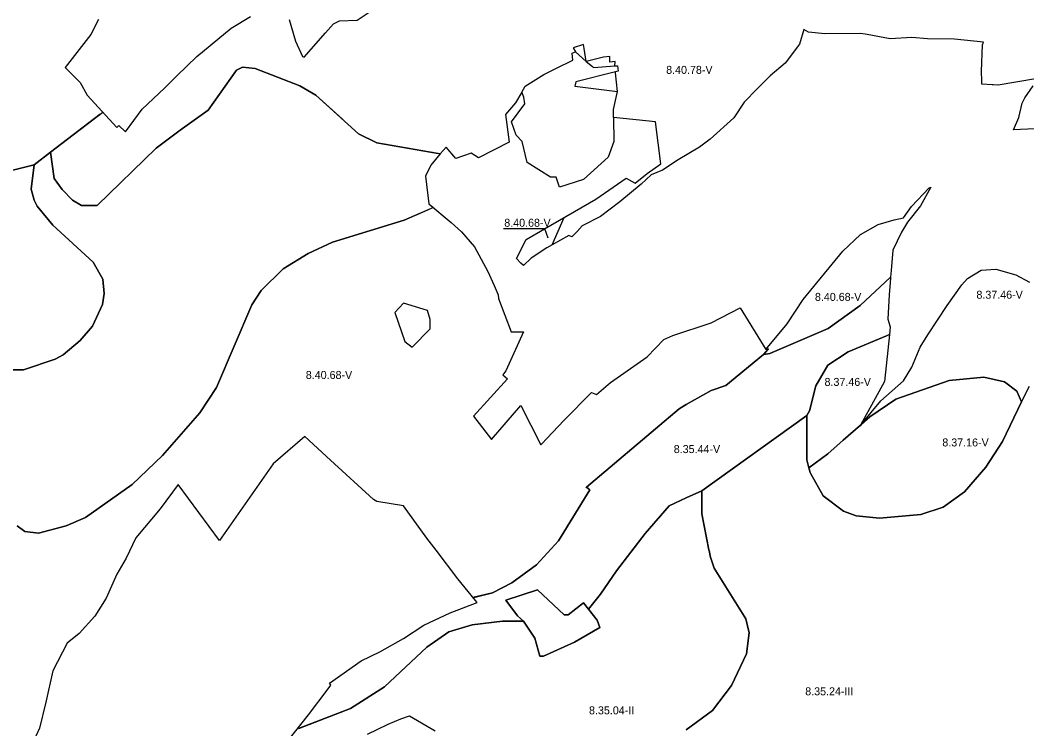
# Model space of a CAD drawing. Extents: x -547623 to -533936, y -1096714 to -1086523.
# Drawn here: x -545832 to -544574, y -1095680 to -1094794 of the extents above; entities that cross this region are included whole.
import ezdxf

# ---------------------------------------------------------------- set-up
doc = ezdxf.new("R2010")
doc.units = 0
doc.layers.add('Vrstva 27', color=7, linetype='Continuous')
doc.layers.add('Vrstva 28', color=7, linetype='Continuous')

msp = doc.modelspace()

# ---------------------------------------------------------------- linework, layer by layer
at = {"layer": 'Vrstva 27'}
msp.add_lwpolyline([(-545228.3, -1095054.4), (-545177.3, -1095054.4), (-545173.1, -1095066.3)], dxfattribs=at)
at = {"layer": 'Vrstva 28'}
for p, q in [((-545597.5, -1094906.5), (-545562, -1094856.5)), ((-545562, -1094856.5), (-545597.5, -1094906.5)), ((-545562, -1094856.5), (-545554.5, -1094853)), ((-545554.5, -1094853), (-545562, -1094856.5)), ((-545554.5, -1094853), (-545538.5, -1094854.5)), ((-545538.5, -1094854.5), (-545554.5, -1094853)), ((-545538.5, -1094854.5), (-545483, -1094876)), ((-545483, -1094876), (-545538.5, -1094854.5)), ((-545483, -1094876), (-545463, -1094888)), ((-545463, -1094888), (-545483, -1094876)), ((-545463, -1094888), (-545409.5, -1094936)), ((-545409.5, -1094936), (-545463, -1094888)), ((-545794.5, -1094959), (-545729, -1094909.2)), ((-545632.5, -1094931.5), (-545597.5, -1094906.5)), ((-545597.5, -1094906.5), (-545632.5, -1094931.5)), ((-545662.5, -1094954), (-545632.5, -1094931.5)), ((-545632.5, -1094931.5), (-545662.5, -1094954)), ((-545409.5, -1094936), (-545386.5, -1094947.5)), ((-545386.5, -1094947.5), (-545409.5, -1094936)), ((-545386.5, -1094947.5), (-545309.8, -1094960.7)), ((-545309.8, -1094960.7), (-545386.5, -1094947.5)), ((-545815, -1094975), (-545794.5, -1094959)), ((-545794.5, -1094959), (-545790, -1094992)), ((-545790, -1094992), (-545794.5, -1094959)), ((-545736, -1095026), (-545662.5, -1094954)), ((-545662.5, -1094954), (-545736, -1095026)), ((-545307.3, -1094961.2), (-545309.8, -1094960.7)), ((-545845, -1094982.5), (-545815, -1094975)), ((-545815, -1094975), (-545818.5, -1095005.5)), ((-545818.5, -1095005.5), (-545815, -1094975)), ((-545790, -1094992), (-545780, -1095006)), ((-545780, -1095006), (-545790, -1094992)), ((-545818.5, -1095005.5), (-545815, -1095019)), ((-545815, -1095019), (-545818.5, -1095005.5)), ((-545780, -1095006), (-545767, -1095019)), ((-545767, -1095019), (-545780, -1095006)), ((-545815, -1095019), (-545811, -1095026.5)), ((-545811, -1095026.5), (-545815, -1095019)), ((-545811, -1095026.5), (-545791.5, -1095050.5)), ((-545791.5, -1095050.5), (-545811, -1095026.5)), ((-545767, -1095019), (-545755.5, -1095026)), ((-545755.5, -1095026), (-545767, -1095019)), ((-545755.5, -1095026), (-545736, -1095026)), ((-545736, -1095026), (-545755.5, -1095026)), ((-545315.9, -1095028.4), (-545352.5, -1095044)), ((-545352.5, -1095044), (-545322.9, -1095031.4)), ((-545791.5, -1095050.5), (-545741, -1095096.5)), ((-545741, -1095096.5), (-545791.5, -1095050.5)), ((-545352.5, -1095044), (-545442, -1095071.5)), ((-545442, -1095071.5), (-545352.5, -1095044)), ((-545442, -1095071.5), (-545472.5, -1095086)), ((-545472.5, -1095086), (-545442, -1095071.5)), ((-545472.5, -1095086), (-545503.5, -1095105)), ((-545503.5, -1095105), (-545472.5, -1095086)), ((-545741, -1095096.5), (-545729, -1095118)), ((-545729, -1095118), (-545741, -1095096.5)), ((-545503.5, -1095105), (-545531, -1095132)), ((-545531, -1095132), (-545503.5, -1095105)), ((-545729, -1095118), (-545727.5, -1095136)), ((-545727.5, -1095136), (-545729, -1095118)), ((-544782.5, -1095151), (-544744.8, -1095115.5)), ((-544744.8, -1095115.5), (-544782.5, -1095151)), ((-545727.5, -1095136), (-545729.5, -1095149.5)), ((-545729.5, -1095149.5), (-545727.5, -1095136)), ((-545531, -1095132), (-545543, -1095150)), ((-545543, -1095150), (-545531, -1095132)), ((-545729.5, -1095149.5), (-545742, -1095176.5)), ((-545742, -1095176.5), (-545729.5, -1095149.5)), ((-545543, -1095150), (-545587, -1095253.5)), ((-545587, -1095253.5), (-545543, -1095150)), ((-544822.5, -1095179.5), (-544782.5, -1095151)), ((-544782.5, -1095151), (-544822.5, -1095179.5)), ((-545742, -1095176.5), (-545757.5, -1095194.5)), ((-545757.5, -1095194.5), (-545742, -1095176.5)), ((-544895.5, -1095211), (-544822.5, -1095179.5)), ((-544822.5, -1095179.5), (-544895.5, -1095211)), ((-544749.7, -1095188.6), (-544797.5, -1095209)), ((-544797.5, -1095209), (-544749.7, -1095188.6)), ((-544746.2, -1095187.1), (-544749.7, -1095188.6)), ((-544749.7, -1095188.6), (-544746.2, -1095187.1)), ((-545757.5, -1095194.5), (-545778.5, -1095212.5)), ((-545778.5, -1095212.5), (-545757.5, -1095194.5)), ((-545778.5, -1095212.5), (-545788.5, -1095218)), ((-545788.5, -1095218), (-545778.5, -1095212.5)), ((-544950.5, -1095251), (-544903.5, -1095212)), ((-544903.5, -1095212), (-544950.5, -1095251)), ((-544903.5, -1095212), (-544897.5, -1095205.5)), ((-544897.5, -1095205.5), (-544903.5, -1095212)), ((-544903.5, -1095212), (-544895.5, -1095211)), ((-544895.5, -1095211), (-544903.5, -1095212)), ((-544897.5, -1095205.5), (-544898.6, -1095203.6)), ((-544898.1, -1095204.5), (-544897.5, -1095205.5)), ((-544797.5, -1095209), (-544823, -1095225.5)), ((-544823, -1095225.5), (-544797.5, -1095209)), ((-545788.5, -1095218), (-545828, -1095231.5)), ((-545828, -1095231.5), (-545788.5, -1095218)), ((-544823, -1095225.5), (-544838, -1095251.5)), ((-544838, -1095251.5), (-544823, -1095225.5)), ((-545828, -1095231.5), (-545842.5, -1095231.5)), ((-545842.5, -1095231.5), (-545828, -1095231.5)), ((-544671.5, -1095244.5), (-544628, -1095240.5)), ((-544628, -1095240.5), (-544671.5, -1095244.5)), ((-544628, -1095240.5), (-544602.5, -1095246.5)), ((-544602.5, -1095246.5), (-544628, -1095240.5)), ((-545587, -1095253.5), (-545608, -1095285)), ((-545608, -1095285), (-545587, -1095253.5)), ((-544969, -1095257), (-544950.5, -1095251)), ((-544950.5, -1095251), (-544969, -1095257)), ((-544838, -1095251.5), (-544846, -1095282.5)), ((-544846, -1095282.5), (-544838, -1095251.5)), ((-544738, -1095268), (-544671.5, -1095244.5)), ((-544671.5, -1095244.5), (-544738, -1095268)), ((-544602.5, -1095246.5), (-544587, -1095258)), ((-544587, -1095258), (-544602.5, -1095246.5)), ((-544581, -1095271.5), (-544571.5, -1095252)), ((-544571.5, -1095252), (-544581, -1095271.5)), ((-545000, -1095274.8), (-544969, -1095257)), ((-544969, -1095257), (-545000, -1095274.8)), ((-544587, -1095258), (-544581, -1095271.5)), ((-544581, -1095271.5), (-544587, -1095258)), ((-545009, -1095280), (-545000, -1095274.8)), ((-545000, -1095274.8), (-545009, -1095280)), ((-544770.5, -1095290), (-544738, -1095268)), ((-544738, -1095268), (-544770.5, -1095290)), ((-544605, -1095321), (-544581, -1095271.5)), ((-544581, -1095271.5), (-544605, -1095321)), ((-545608, -1095285), (-545654.5, -1095338.5)), ((-545654.5, -1095338.5), (-545608, -1095285)), ((-545038.5, -1095305), (-545009, -1095280)), ((-545009, -1095280), (-545038.5, -1095305)), ((-544980.5, -1095382.5), (-544849.5, -1095288.5)), ((-544849.5, -1095288.5), (-544980.5, -1095382.5)), ((-544846, -1095282.5), (-544849.5, -1095288.5)), ((-544849.5, -1095288.5), (-544846, -1095282.5)), ((-544849.5, -1095288.5), (-544849.5, -1095344)), ((-544849.5, -1095344), (-544849.5, -1095288.5)), ((-544781, -1095299.3), (-544770.5, -1095290)), ((-544770.5, -1095290), (-544781, -1095299.3)), ((-544804, -1095319.3), (-544782.1, -1095300.3)), ((-544782.1, -1095300.3), (-544804, -1095319.3)), ((-544782.1, -1095300.3), (-544782.1, -1095300.3)), ((-544782.1, -1095300.3), (-544782.1, -1095300.3)), ((-544782.1, -1095300.3), (-544782.1, -1095300.3)), ((-545124.5, -1095378), (-545038.5, -1095305)), ((-545038.5, -1095305), (-545124.5, -1095378)), ((-544823.2, -1095336.2), (-544804, -1095319.3)), ((-544804, -1095319.3), (-544823.2, -1095336.2)), ((-544625.5, -1095353), (-544605, -1095321)), ((-544605, -1095321), (-544625.5, -1095353)), ((-545654.5, -1095338.5), (-545692.5, -1095374.5)), ((-545692.5, -1095374.5), (-545654.5, -1095338.5)), ((-544846.7, -1095353.9), (-544823.2, -1095336.2)), ((-544823.2, -1095336.2), (-544846.7, -1095353.9)), ((-544849.5, -1095344), (-544846.7, -1095353.9)), ((-544846.7, -1095353.9), (-544849.5, -1095344)), ((-544846.7, -1095353.9), (-544845, -1095359.7)), ((-544845, -1095359.7), (-544846.7, -1095353.9)), ((-544652.5, -1095384), (-544625.5, -1095353)), ((-544625.5, -1095353), (-544652.5, -1095384)), ((-544845, -1095359.7), (-544844.5, -1095361.5)), ((-544844.5, -1095361.5), (-544845, -1095359.7)), ((-544844.5, -1095361.5), (-544829, -1095389)), ((-544829, -1095389), (-544844.5, -1095361.5)), ((-545692.5, -1095374.5), (-545750.5, -1095416)), ((-545750.5, -1095416), (-545692.5, -1095374.5)), ((-545124.5, -1095378), (-545125.3, -1095378.7)), ((-545120.5, -1095381.5), (-545124.5, -1095378)), ((-545124.5, -1095378), (-545120.5, -1095381.5)), ((-545159.5, -1095445), (-545120.5, -1095381.5)), ((-545120.5, -1095381.5), (-545159.5, -1095445)), ((-545021.5, -1095401.5), (-545000, -1095391.5)), ((-545000, -1095391.5), (-545021.5, -1095401.5)), ((-545000, -1095391.5), (-544980.5, -1095382.5)), ((-544980.5, -1095382.5), (-545000, -1095391.5)), ((-544980.5, -1095382.5), (-544980.5, -1095411.5)), ((-544980.5, -1095411.5), (-544980.5, -1095382.5)), ((-544829, -1095389), (-544803.5, -1095408)), ((-544803.5, -1095408), (-544829, -1095389)), ((-544679, -1095403), (-544652.5, -1095384)), ((-544652.5, -1095384), (-544679, -1095403)), ((-545051.5, -1095436), (-545021.5, -1095401.5)), ((-545021.5, -1095401.5), (-545051.5, -1095436)), ((-544707, -1095412), (-544679, -1095403)), ((-544679, -1095403), (-544707, -1095412)), ((-545750.5, -1095416), (-545775, -1095426.5)), ((-545775, -1095426.5), (-545750.5, -1095416)), ((-544980.5, -1095411.5), (-544971.6, -1095456.2)), ((-544971.6, -1095456.2), (-544980.5, -1095411.5)), ((-544803.5, -1095408), (-544787.5, -1095414)), ((-544787.5, -1095414), (-544803.5, -1095408)), ((-544787.5, -1095414), (-544758.5, -1095417)), ((-544758.5, -1095417), (-544787.5, -1095414)), ((-544758.5, -1095417), (-544707, -1095412)), ((-544707, -1095412), (-544758.5, -1095417)), ((-545826.5, -1095433.5), (-545836, -1095426.5)), ((-545836, -1095426.5), (-545826.5, -1095433.5)), ((-545775, -1095426.5), (-545809.5, -1095435.5)), ((-545809.5, -1095435.5), (-545775, -1095426.5)), ((-545809.5, -1095435.5), (-545826.5, -1095433.5)), ((-545826.5, -1095433.5), (-545809.5, -1095435.5)), ((-545087, -1095482.5), (-545051.5, -1095436)), ((-545051.5, -1095436), (-545087, -1095482.5)), ((-545187, -1095475), (-545159.5, -1095445)), ((-545159.5, -1095445), (-545187, -1095475)), ((-544971.6, -1095456.2), (-544971.1, -1095459)), ((-544971.1, -1095459), (-544971.6, -1095456.2)), ((-544971.1, -1095459), (-544970, -1095464.5)), ((-544970, -1095464.5), (-544971.1, -1095459)), ((-544970, -1095464.5), (-544965, -1095479.5)), ((-544965, -1095479.5), (-544970, -1095464.5)), ((-545218, -1095497.5), (-545187, -1095475)), ((-545187, -1095475), (-545218, -1095497.5)), ((-544965, -1095479.5), (-544925.5, -1095542.5)), ((-544925.5, -1095542.5), (-544965, -1095479.5)), ((-545107, -1095512), (-545087, -1095482.5)), ((-545087, -1095482.5), (-545107, -1095512)), ((-545242, -1095510), (-545218, -1095497.5)), ((-545218, -1095497.5), (-545242, -1095510)), ((-545242, -1095510), (-545266.5, -1095516)), ((-545225.5, -1095519.5), (-545186, -1095506.5)), ((-545186, -1095506.5), (-545152.5, -1095537.5)), ((-545122.2, -1095530.7), (-545107, -1095512)), ((-545107, -1095512), (-545122.2, -1095530.7)), ((-545211, -1095539), (-545225.5, -1095519.5)), ((-545128.5, -1095522.5), (-545147.5, -1095537.5)), ((-545147.5, -1095537.5), (-545128.5, -1095522.5)), ((-545122.2, -1095530.7), (-545128.5, -1095522.5)), ((-545128.5, -1095522.5), (-545122.2, -1095530.7)), ((-545211, -1095539), (-545203.5, -1095545.5)), ((-545203.5, -1095545.5), (-545211, -1095539)), ((-545147.5, -1095537.5), (-545152.5, -1095537.5)), ((-545152.5, -1095537.5), (-545147.5, -1095537.5)), ((-545111.5, -1095544.5), (-545122.2, -1095530.7)), ((-545122.2, -1095530.7), (-545111.5, -1095544.5)), ((-544925.5, -1095542.5), (-544921.5, -1095560)), ((-544921.5, -1095560), (-544925.5, -1095542.5)), ((-545267.5, -1095550), (-545296.5, -1095559)), ((-545229.5, -1095545.5), (-545267.5, -1095550)), ((-545203.5, -1095545.5), (-545229.5, -1095545.5)), ((-545203.5, -1095545.5), (-545189, -1095567)), ((-545189, -1095567), (-545203.5, -1095545.5)), ((-545139.5, -1095572), (-545108, -1095553.5)), ((-545108, -1095553.5), (-545139.5, -1095572)), ((-545108, -1095553.5), (-545111.5, -1095544.5)), ((-545111.5, -1095544.5), (-545108, -1095553.5)), ((-545296.5, -1095559), (-545324, -1095578)), ((-545189, -1095567), (-545183, -1095589.5)), ((-545183, -1095589.5), (-545189, -1095567)), ((-544921.5, -1095560), (-544924.5, -1095586.5)), ((-544924.5, -1095586.5), (-544921.5, -1095560)), ((-545324, -1095578), (-545377, -1095627.5)), ((-545178.5, -1095589.5), (-545139.5, -1095572)), ((-545139.5, -1095572), (-545178.5, -1095589.5)), ((-545183, -1095589.5), (-545178.5, -1095589.5)), ((-545178.5, -1095589.5), (-545183, -1095589.5)), ((-544924.5, -1095586.5), (-544943.5, -1095626)), ((-544943.5, -1095626), (-544924.5, -1095586.5)), ((-545377, -1095627.5), (-545419.5, -1095655)), ((-544943.5, -1095626), (-544967, -1095657.5)), ((-544967, -1095657.5), (-544943.5, -1095626)), ((-545419.5, -1095655), (-545484.5, -1095679.9)), ((-544967, -1095657.5), (-545000, -1095681.3)), ((-545000, -1095681.3), (-544967, -1095657.5))]:
    msp.add_line(p, q, dxfattribs=at)
for points in [[(-545496, -1094793.4), (-545488.2, -1094820.5), (-545479.4, -1094839.5), (-545477.6, -1094840.2), (-545450.7, -1094809.9), (-545440.8, -1094798.6), (-545433.3, -1094795), (-545411.4, -1094794), (-545391.2, -1094780.8)], [(-545734.6, -1094793.4), (-545744.1, -1094812.1), (-545776.1, -1094853.2), (-545757.5, -1094871.9), (-545748.7, -1094887.7), (-545711.5, -1094928.4), (-545708.9, -1094925.6), (-545700.5, -1094933.9), (-545680, -1094905.5), (-545652, -1094879.2), (-545636.5, -1094863.8), (-545611.7, -1094839.5), (-545568.6, -1094803.9), (-545544.4, -1094789.6)], [(-544617.6, -1094874.8), (-544630.7, -1094874), (-544630.8, -1094870.1), (-544631.1, -1094858.4), (-544631.5, -1094858.4), (-544631.1, -1094858.4), (-544631.2, -1094858.3), (-544629.8, -1094825.1), (-544628.5, -1094821.5), (-544664.6, -1094818), (-544698.4, -1094817.2), (-544717.9, -1094815.8), (-544745.1, -1094817.4), (-544774.1, -1094811.8), (-544781.7, -1094810.9), (-544826.7, -1094811.2), (-544847.2, -1094809.1), (-544852.9, -1094805.7), (-544858.3, -1094824), (-544876.4, -1094847.7), (-544895, -1094863.8), (-544911.4, -1094879.8), (-544927.7, -1094896.5), (-544940.6, -1094916.1), (-544970.1, -1094942.7), (-544983.4, -1094952.9), (-545010.2, -1094968.6), (-545029.6, -1094981.6), (-545043.9, -1094987.4), (-545056.3, -1094999.1), (-545082.9, -1095021.3), (-545107.3, -1095039.6), (-545130.2, -1095051.2), (-545136.3, -1095058.2), (-545142.8, -1095065.2), (-545146.7, -1095063.3), (-545167.5, -1095074.8), (-545174.2, -1095078.6), (-545193.8, -1095091.5), (-545203.2, -1095100.7), (-545206.5, -1095097.9), (-545212.2, -1095091.9), (-545199.9, -1095068.4), (-545177.1, -1095055.1), (-545113.1, -1095017.7), (-545074.9, -1094991.6), (-545064, -1094997.8), (-545049, -1094985.8), (-545031.7, -1094973.6), (-545038.5, -1094921.2), (-545090.9, -1094915.7), (-545090.9, -1094916.1), (-545090.5, -1094945.8), (-545097.6, -1094965.4), (-545128.4, -1094993.3), (-545158.4, -1095002.7), (-545162.6, -1094990.2), (-545169.8, -1094990.4), (-545198.8, -1094972.1), (-545205.2, -1094945.7), (-545212.7, -1094937.8), (-545218.2, -1094921.3), (-545201.7, -1094898.7), (-545202.8, -1094890.4), (-545205.5, -1094884.1), (-545205.5, -1094884), (-545213.4, -1094897.3), (-545225.7, -1094912.1), (-545221.1, -1094946.5), (-545259.7, -1094966), (-545268.9, -1094960.5), (-545288, -1094967.2), (-545300.1, -1094952.7), (-545307.3, -1094961.2), (-545319.1, -1094975.2), (-545325.8, -1094989.3), (-545321.5, -1095023.7), (-545293.6, -1095047.2), (-545281, -1095058.7), (-545264.8, -1095077.3), (-545247.9, -1095108.2), (-545240, -1095126), (-545235.2, -1095137.5), (-545234.5, -1095141.9), (-545218.6, -1095183.9), (-545203.5, -1095183.8), (-545225.3, -1095232.6), (-545229.3, -1095237.4), (-545223.5, -1095242.4), (-545265.9, -1095289.1), (-545243.2, -1095318.4), (-545206.5, -1095275.9), (-545181.7, -1095325.2), (-545180.6, -1095323.9), (-545174.3, -1095317.1), (-545152.4, -1095294.1), (-545118.3, -1095259.6), (-545112.3, -1095262.2), (-545094.5, -1095247.2), (-545048.7, -1095215), (-545028.2, -1095193.2), (-545016.9, -1095188.3), (-544968.8, -1095172.4), (-544932.7, -1095153.8), (-544900.6, -1095206), (-544874, -1095173.9), (-544854, -1095143.4), (-544804.2, -1095083), (-544782.1, -1095062.1), (-544760.2, -1095049.6), (-544740, -1095043.6), (-544728.7, -1095041.4), (-544718.5, -1095027.1), (-544696.5, -1095003.8), (-544694.2, -1095002.9), (-544707.3, -1095026.1), (-544723.5, -1095046.8), (-544730.9, -1095059.1), (-544741.8, -1095081.6), (-544744, -1095106.9), (-544744.4, -1095111.3), (-544744.8, -1095115.5), (-544744.9, -1095116.6), (-544745.3, -1095122.3), (-544746.3, -1095137.4), (-544748, -1095168.1), (-544745.3, -1095177.5), (-544746.2, -1095187.1), (-544752.2, -1095246.1), (-544782.1, -1095300.3), (-544782.8, -1095301.4), (-544781, -1095299.3), (-544757, -1095270), (-544728.4, -1095244.9), (-544717.9, -1095228), (-544707.8, -1095202.8), (-544698.1, -1095187.4), (-544673.8, -1095150.8), (-544655.6, -1095125), (-544648.6, -1095117.1), (-544631.3, -1095106.8), (-544613.3, -1095105.4), (-544588, -1095112.6), (-544571.2, -1095121.7)], [(-545125, -1094845.8), (-545127.6, -1094829.3), (-545128.3, -1094824.6), (-545141.5, -1094828.6), (-545138.5, -1094833.6), (-545125, -1094845.8)], [(-545205.5, -1094884), (-545201.1, -1094876.5), (-545178.1, -1094861.9), (-545162.3, -1094853.9), (-545141.8, -1094844.2), (-545142.6, -1094835.2), (-545138.5, -1094833.6)], [(-545117.1, -1094852), (-545115.8, -1094853.2), (-545089.1, -1094851.3), (-545089, -1094845.6), (-545095.5, -1094846.4), (-545095.4, -1094839.3), (-545103.2, -1094840.4), (-545125, -1094845.8), (-545117.1, -1094852)], [(-545089.1, -1094851.3), (-545085.7, -1094851), (-545085.1, -1094857.9), (-545088.5, -1094858.5)], [(-545409.5, -1094936), (-545463, -1094888), (-545483, -1094876), (-545538.5, -1094854.5), (-545554.5, -1094853), (-545562, -1094856.5), (-545597.5, -1094906.5), (-545632.5, -1094931.5), (-545662.5, -1094954), (-545736, -1095026), (-545755.5, -1095026), (-545767, -1095019), (-545780, -1095006), (-545790, -1094992), (-545794.5, -1094959), (-545815, -1094975), (-545818.5, -1095005.5), (-545815, -1095019), (-545811, -1095026.5), (-545791.5, -1095050.5), (-545741, -1095096.5), (-545729, -1095118), (-545727.5, -1095136), (-545729.5, -1095149.5), (-545742, -1095176.5), (-545757.5, -1095194.5), (-545778.5, -1095212.5), (-545788.5, -1095218), (-545828, -1095231.5), (-545842.5, -1095231.5)], [(-545732.5, -1094911.8), (-545794.5, -1094959), (-545790, -1094992), (-545780, -1095006), (-545767, -1095019), (-545755.5, -1095026), (-545736, -1095026), (-545662.5, -1094954), (-545632.5, -1094931.5), (-545597.5, -1094906.5), (-545562, -1094856.5), (-545554.5, -1094853), (-545538.5, -1094854.5), (-545483, -1094876), (-545463, -1094888), (-545429.7, -1094917.9)], [(-545088.4, -1094859.9), (-545088.5, -1094858.5), (-545138.1, -1094871.2), (-545139.4, -1094876.5), (-545085.9, -1094883.2), (-545088.4, -1094859.9)], [(-544563.6, -1094867.3), (-544610.2, -1094875.2), (-544616.5, -1094874.8), (-544617.5, -1094875), (-544617.6, -1094874.8)], [(-544529, -1094928.4), (-544591.1, -1094931.1), (-544584.4, -1094915.6), (-544580.1, -1094897.9), (-544576.8, -1094891.1), (-544566.4, -1094876.1)], [(-545090.9, -1094915.7), (-545091, -1094905.7), (-545085.9, -1094883.2)], [(-545842.5, -1095231.5), (-545828, -1095231.5), (-545788.5, -1095218), (-545778.5, -1095212.5), (-545757.5, -1095194.5), (-545742, -1095176.5), (-545729.5, -1095149.5), (-545727.5, -1095136), (-545729, -1095118), (-545741, -1095096.5), (-545791.5, -1095050.5), (-545811, -1095026.5), (-545815, -1095019), (-545818.5, -1095005.5), (-545815, -1094975), (-545845, -1094982.5)], [(-545167.5, -1095074.8), (-545152.7, -1095040.9)], [(-544744.8, -1095115.5), (-544782.5, -1095151), (-544822.5, -1095179.5), (-544895.5, -1095211), (-544903.5, -1095212), (-544950.5, -1095251), (-544969, -1095257), (-545000, -1095274.8), (-545009, -1095280), (-545038.5, -1095305), (-545124.5, -1095378), (-545120.5, -1095381.5), (-545159.5, -1095445), (-545187, -1095475), (-545218, -1095497.5), (-545242, -1095510), (-545265.6, -1095515.8)], [(-545351.6, -1095196), (-545342.3, -1095203.1), (-545320, -1095180.1), (-545320.1, -1095168.4), (-545323.3, -1095157.3), (-545353.5, -1095148.1), (-545364, -1095159.6), (-545351.6, -1095196)], [(-545484.3, -1095679.8), (-545419.5, -1095655), (-545377, -1095627.5), (-545324, -1095578), (-545296.5, -1095559), (-545267.5, -1095550), (-545229.5, -1095545.5), (-545203.5, -1095545.5), (-545211, -1095539), (-545225.5, -1095519.5), (-545186, -1095506.5), (-545152.5, -1095537.5), (-545147.5, -1095537.5), (-545128.5, -1095522.5), (-545122.2, -1095530.7), (-545107, -1095512), (-545087, -1095482.5), (-545051.5, -1095436), (-545021.5, -1095401.5), (-545000, -1095391.5), (-544980.5, -1095382.5), (-544849.5, -1095288.5), (-544846, -1095282.5), (-544838, -1095251.5), (-544823, -1095225.5), (-544797.5, -1095209), (-544749.7, -1095188.6), (-544746.2, -1095187.1)], [(-544782.1, -1095300.3), (-544804, -1095319.3), (-544823.2, -1095336.2), (-544846.7, -1095353.9), (-544845, -1095359.7), (-544844.5, -1095361.5), (-544829, -1095389), (-544803.5, -1095408), (-544787.5, -1095414), (-544758.5, -1095417), (-544707, -1095412), (-544679, -1095403), (-544652.5, -1095384), (-544625.5, -1095353), (-544605, -1095321), (-544581, -1095271.5), (-544587, -1095258), (-544602.5, -1095246.5), (-544628, -1095240.5), (-544671.5, -1095244.5)], [(-544671.5, -1095244.5), (-544738, -1095268), (-544770.5, -1095290), (-544781, -1095299.3)], [(-544781, -1095299.3), (-544782.8, -1095301.4), (-544782.1, -1095300.3)], [(-545294.9, -1095535), (-545261.1, -1095522.2), (-545263.3, -1095519.7), (-545285.3, -1095492.8), (-545312.4, -1095457), (-545324, -1095441.7), (-545353.2, -1095401.5), (-545386.7, -1095396), (-545390.8, -1095393.6), (-545444.5, -1095344.4), (-545476.8, -1095314.6), (-545516.3, -1095348.7), (-545580.3, -1095440.6), (-545583.4, -1095444.8), (-545635, -1095374.7), (-545657.5, -1095405.2), (-545687.8, -1095441.4), (-545700, -1095466.8), (-545711.6, -1095487), (-545725, -1095516.9), (-545738.9, -1095539.2), (-545758.8, -1095561.1), (-545773.8, -1095573.2), (-545791.4, -1095607.8), (-545800.4, -1095646.7), (-545808, -1095679.3), (-545822, -1095709.3)], [(-545265.5, -1095515.8), (-545242, -1095510), (-545218, -1095497.5), (-545187, -1095475), (-545159.5, -1095445), (-545120.5, -1095381.5), (-545124.5, -1095378)], [(-545152.5, -1095537.5), (-545186, -1095506.5), (-545225.5, -1095519.5), (-545211, -1095539), (-545203.5, -1095545.5), (-545189, -1095567), (-545183, -1095589.5), (-545178.5, -1095589.5), (-545139.5, -1095572), (-545108, -1095553.5), (-545111.5, -1095544.5), (-545122.2, -1095530.7), (-545128.5, -1095522.5), (-545147.5, -1095537.5), (-545152.5, -1095537.5)], [(-545541.8, -1095751), (-545472.2, -1095662.6), (-545447.6, -1095630.1), (-545444.1, -1095625.5), (-545445.9, -1095623), (-545406.1, -1095595.3), (-545382.7, -1095584.1), (-545353.2, -1095567.2), (-545328, -1095550.6), (-545294.9, -1095535)], [(-545398.5, -1095686.9), (-545372.5, -1095674.4), (-545356.8, -1095667.6), (-545346, -1095663.8), (-545313.8, -1095682.8)]]:
    msp.add_lwpolyline(points, dxfattribs=at)

# ---------------------------------------------------------------- texts
at = {"layer": 'Vrstva 27'}
for s, p in [('8.40.78-V', (-545025.1, -1094861.2)), ('8.40.68-V', (-545227.4, -1095052.4)), ('8.40.68-V', (-544839.2, -1095145.1)), ('8.37.46-V', (-544637.4, -1095142.4)), ('8.40.68-V', (-545475.4, -1095242.7)), ('8.37.46-V', (-544827.2, -1095251.4)), ('8.35.44-V', (-545015.6, -1095335.4)), ('8.37.16-V', (-544680, -1095327.1)), ('8.35.24-III', (-544851.3, -1095638.3)), ('8.35.04-II', (-545121.5, -1095662.1))]:
    msp.add_text(s, height=10, dxfattribs=at).set_placement(p)

doc.saveas('drawing.dxf')
